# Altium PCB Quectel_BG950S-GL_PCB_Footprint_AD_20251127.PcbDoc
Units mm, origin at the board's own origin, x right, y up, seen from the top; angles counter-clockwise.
Board outline 152.4 x 101.6 mm, 2 copper layers (Top Layer, Bottom Layer); 1 components, 0 nets, 102 pads, 0 vias.
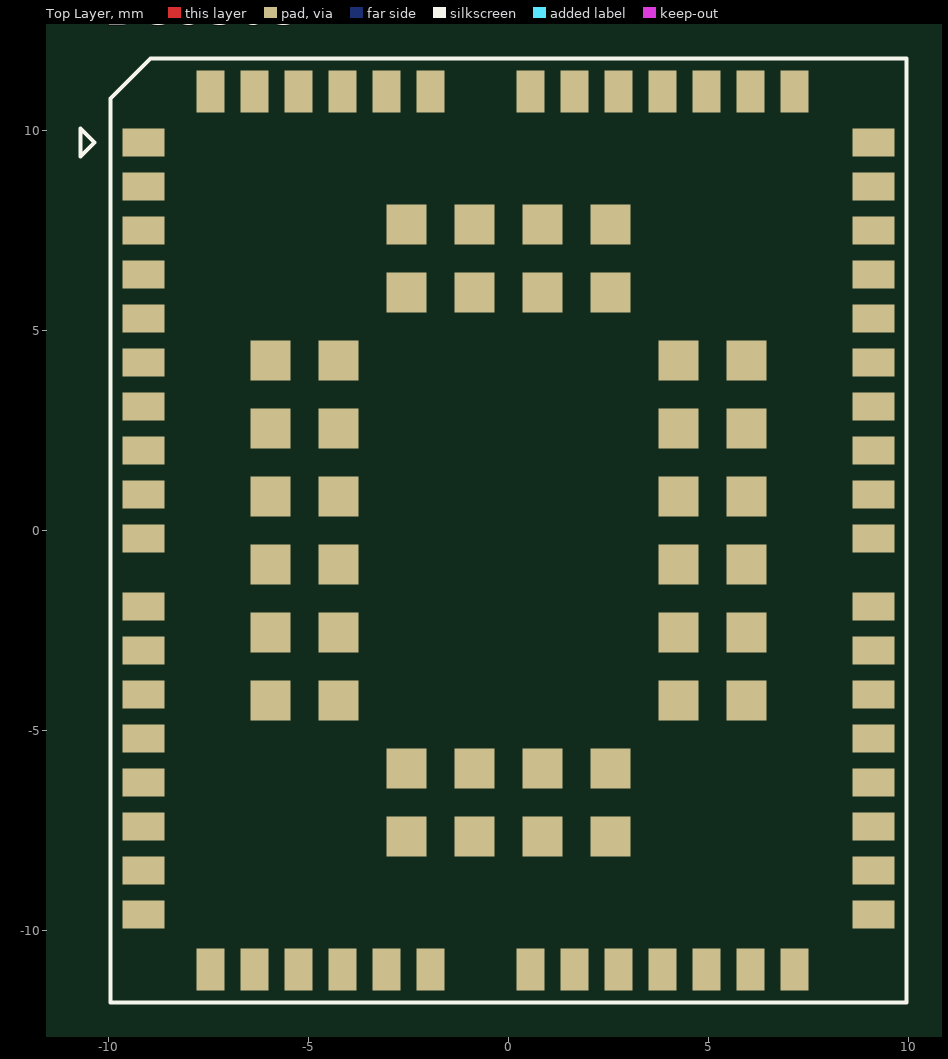
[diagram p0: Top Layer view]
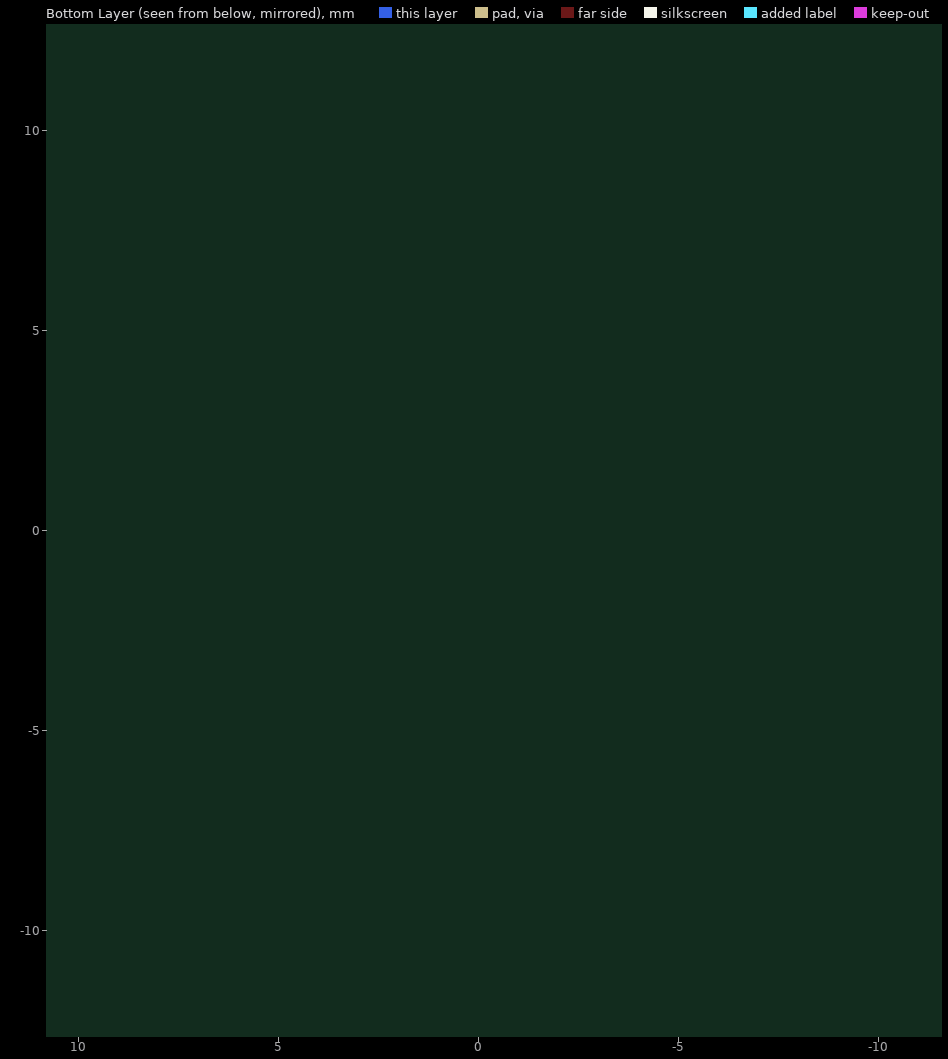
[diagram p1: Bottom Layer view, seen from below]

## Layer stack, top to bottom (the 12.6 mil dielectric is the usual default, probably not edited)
Top Solder: solder mask 0.0102, Solder Resist, Dk 3.5
Top Layer: signal copper 0.0356
Dielectric1: dielectric 0.32, FR-4, Dk 4.8
Bottom Layer: signal copper 0.0356
Bottom Solder: solder mask 0.0102, Solder Resist, Dk 3.5

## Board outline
-70.739,-53.721 81.661,-53.721 81.661,47.879 -70.739,47.879

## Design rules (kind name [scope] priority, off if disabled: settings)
Clearance [All] p1: gap=0.254 ignorepadtopadclearanceinfootprint=FALSE except(0: Arc-Hole Track-Hole SMDPad-Hole THPad-Hole Via-Hole Fill-Hole Poly-Hole Region-Hole Text-Hole)
PolygonConnect [All] p1: connectstyle=Relief reliefconductorwidth=0.254 reliefentries=4 polygonreliefangle="90 Angle" airgapwidth=0.254
RoutingVias [All] p1: holewidth=0.711 width=1.27 viastyle="Through Hole" minholewidth=0.711 minwidth=1.27 maxholewidth=0.711 maxwidth=1.27
SolderMaskExpansion [All] p1: expansion=0.102 istentingtop=FALSE
Width [All] p1: maxlimit=0.254 minlimit=0.254 preferedwidth=0.254
30 further rules are at their usual default settings.

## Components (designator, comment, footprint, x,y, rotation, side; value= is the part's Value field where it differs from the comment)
BG950S "Comment" BG950S 0,0 r0 top

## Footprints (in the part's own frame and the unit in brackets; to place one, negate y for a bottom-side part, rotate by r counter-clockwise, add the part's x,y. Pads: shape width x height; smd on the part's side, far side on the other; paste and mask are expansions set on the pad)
BG950S [mm] "BG950S-GL Module 102PIN 19.9x23.6mm H2.4mm RO"
  rect 1.05x0.7 smd mask+0.05: 1(-9.125,9.7) 2(-9.125,8.6) 3(-9.125,7.5) 4(-9.125,6.4) 5(-9.125,5.3) 6(-9.125,4.2) 7(-9.125,3.1) 8(-9.125,2) 9(-9.125,0.9) 10(-9.125,-0.2) 11(-9.125,-1.9) 12(-9.125,-3) 13(-9.125,-4.1) 14(-9.125,-5.2) 15(-9.125,-6.3) 16(-9.125,-7.4) 17(-9.125,-8.5) 18(-9.125,-9.6) 32(9.125,-9.6) 33(9.125,-8.5) 34(9.125,-7.4) 35(9.125,-6.3) 36(9.125,-5.2) 37(9.125,-4.1) 38(9.125,-3) 39(9.125,-1.9) 40(9.125,-0.2) 41(9.125,0.9) 42(9.125,2) 43(9.125,3.1) 44(9.125,4.2) 45(9.125,5.3) 46(9.125,6.4) 47(9.125,7.5) 48(9.125,8.6) 49(9.125,9.7)
  rect 0.7x1.05 smd mask+0.05: 19(-7.45,-10.975) 20(-6.35,-10.975) 21(-5.25,-10.975) 22(-4.15,-10.975) 23(-3.05,-10.975) 24(-1.95,-10.975) 25(0.55,-10.975) 26(1.65,-10.975) 27(2.75,-10.975) 28(3.85,-10.975) 29(4.95,-10.975) 30(6.05,-10.975) 31(7.15,-10.975) 50(7.15,10.975) 51(6.05,10.975) 52(4.95,10.975) 53(3.85,10.975) 54(2.75,10.975) 55(1.65,10.975) 56(0.55,10.975) 57(-1.95,10.975) 58(-3.05,10.975) 59(-4.15,10.975) 60(-5.25,10.975) 61(-6.35,10.975) 62(-7.45,10.975)
  rect 1x1 smd mask+0.05: 63(-5.95,4.25) 64(-5.95,2.55) 65(-5.95,0.85) 66(-5.95,-0.85) 67(-5.95,-2.55) 68(-5.95,-4.25) 69(-2.55,-7.65) 70(-0.85,-7.65) 71(0.85,-7.65) 72(2.55,-7.65) 73(5.95,-4.25) 74(5.95,-2.55) 75(5.95,-0.85) 76(5.95,0.85) 77(5.95,2.55) 78(5.95,4.25) 79(2.55,7.65) 80(0.85,7.65) 81(-0.85,7.65) 82(-2.55,7.65) 83(-4.25,4.25) 84(-4.25,2.55) 85(-4.25,0.85) 86(-4.25,-0.85) 87(-4.25,-2.55) 88(-4.25,-4.25) 89(-2.55,-5.95) 90(-0.85,-5.95) 91(0.85,-5.95) 92(2.55,-5.95) 93(4.25,-4.25) 94(4.25,-2.55) 95(4.25,-0.85) 96(4.25,0.85) 97(4.25,2.55) 98(4.25,4.25) 99(2.55,5.95) 100(0.85,5.95) 101(-0.85,5.95) 102(-2.55,5.95)
  silkscreen extent -10.7,-11.8 9.95,11.8, body extent -9.95,-11.8 9.95,11.8, height 2.4

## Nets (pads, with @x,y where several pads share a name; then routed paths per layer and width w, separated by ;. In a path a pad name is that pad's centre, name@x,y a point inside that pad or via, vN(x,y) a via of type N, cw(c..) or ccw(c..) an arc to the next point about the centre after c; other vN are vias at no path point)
pads on no net: BG950S.1 BG950S.2 BG950S.3 BG950S.4 BG950S.5 BG950S.6 BG950S.7 BG950S.8 BG950S.9 BG950S.10 BG950S.11 BG950S.12 BG950S.13 BG950S.14 BG950S.15 BG950S.16 BG950S.17 BG950S.18 BG950S.19 BG950S.20 BG950S.21 BG950S.22 BG950S.23 BG950S.24 BG950S.25 BG950S.26 BG950S.27 BG950S.28 BG950S.29 BG950S.30 BG950S.31 BG950S.32 BG950S.33 BG950S.34 BG950S.35 BG950S.36 BG950S.37 BG950S.38 BG950S.39 BG950S.40 BG950S.41 BG950S.42 BG950S.43 BG950S.44 BG950S.45 BG950S.46 BG950S.47 BG950S.48 BG950S.49 BG950S.50 BG950S.51 BG950S.52 BG950S.53 BG950S.54 BG950S.55 BG950S.56 BG950S.57 BG950S.58 BG950S.59 BG950S.60 BG950S.61 BG950S.62 BG950S.63 BG950S.64 BG950S.65 BG950S.66 BG950S.67 BG950S.68 BG950S.69 BG950S.70 BG950S.71 BG950S.72 BG950S.73 BG950S.74 BG950S.75 BG950S.76 BG950S.77 BG950S.78 BG950S.79 BG950S.80 BG950S.81 BG950S.82 BG950S.83 BG950S.84 BG950S.85 BG950S.86 BG950S.87 BG950S.88 BG950S.89 BG950S.90 BG950S.91 BG950S.92 BG950S.93 BG950S.94 BG950S.95 BG950S.96 BG950S.97 BG950S.98 BG950S.99 BG950S.100 BG950S.101 BG950S.102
